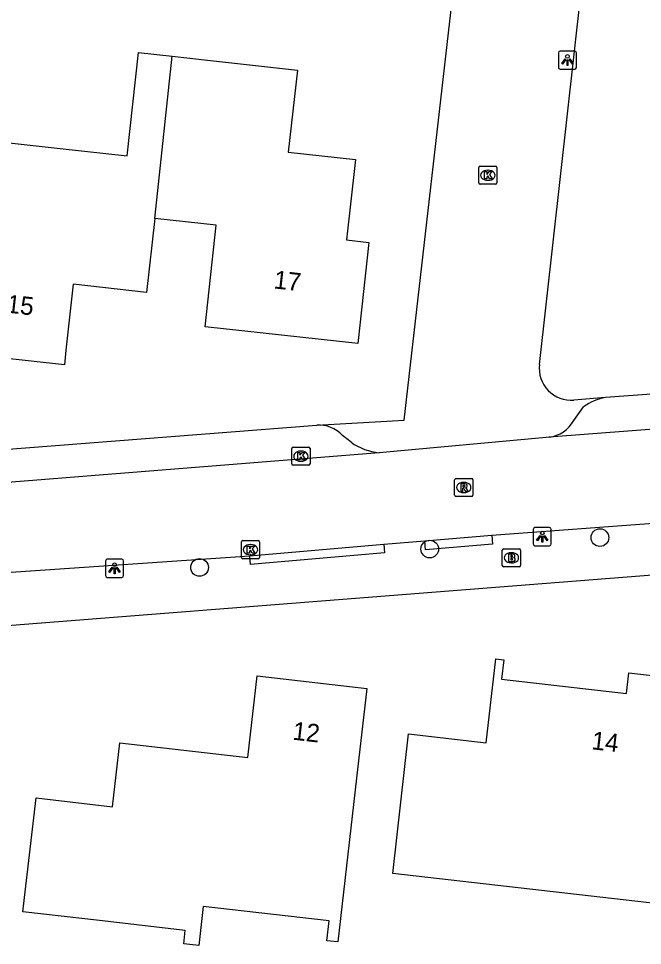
# Model space of a CAD drawing. Extents: x 162398 to 163643, y 386453 to 387397.
# Drawn here: x 163061.6 to 163096.1, y 386543.6 to 386594.8 of the extents above; entities that cross this region are included whole.
import ezdxf

# ---------------------------------------------------------------- set-up
doc = ezdxf.new("R2010")
doc.units = 0
for name, color, linetype in [('IMGEO_Boom', 7, 'Continuous'), ('IMGEO_Brandkraan', 7, 'Continuous'), ('IMGEO_Kolk', 7, 'Continuous'), ('IMGEO_Lichtpunt', 7, 'Continuous'), ('IMGEO_Pand', 7, 'Continuous'), ('IMGEO_Pand_nummerreeks', 7, 'Continuous'), ('IMGEO_Parkeervlak_open', 7, 'Continuous'), ('IMGEO_Rijbaan_lokaal_open', 7, 'Continuous'), ('IMGEO_Rioolput', 7, 'Continuous'), ('IMGEO_Voetpad_open', 7, 'Continuous')]:
    doc.layers.add(name, color=color, linetype=linetype)

msp = doc.modelspace()

# ---------------------------------------------------------------- linework, layer by layer
at = {"layer": 'IMGEO_Boom'}
for centre in [(163093.767, 386566.156), (163084.356, 386565.527), (163071.63, 386564.507)]:
    msp.add_circle(centre, 0.489, dxfattribs=at)
at = {"layer": 'IMGEO_Brandkraan'}
for p, q in [((163088.446, 386565.542), (163089.298, 386565.542)), ((163088.371, 386564.616), (163088.371, 386565.468)), ((163088.859, 386565.322), (163088.884, 386565.322)), ((163089.372, 386565.468), (163089.372, 386564.616)), ((163089.298, 386564.542), (163088.446, 386564.542)), ((163088.882, 386564.762), (163088.857, 386564.762))]:
    msp.add_line(p, q, dxfattribs=at)
for points in [[(163088.446, 386565.542), (163089.298, 386565.542)], [(163088.371, 386564.616), (163088.371, 386565.468)], [(163088.719, 386565.242), (163088.719, 386564.842), (163088.932, 386564.842)], [(163088.95, 386565.242), (163088.719, 386565.242)], [(163088.898, 386565.161), (163088.844, 386565.161), (163088.844, 386565.085)], [(163088.844, 386565.085), (163088.897, 386565.085)], [(163088.906, 386565.009), (163088.844, 386565.009), (163088.844, 386564.928)], [(163089.372, 386565.468), (163089.372, 386564.616)], [(163089.298, 386564.542), (163088.446, 386564.542)], [(163088.844, 386564.928), (163088.906, 386564.928)]]:
    msp.add_lwpolyline(points, dxfattribs=at)
for centre, radius, start, end in [((163088.448, 386565.466), 0.0765, 91.552, 178.448), ((163088.448, 386565.466), 0.0765, 91.552, 178.448), ((163089.296, 386565.466), 0.0765, 1.552, 88.448), ((163089.296, 386565.466), 0.0765, 1.552, 88.448), ((163088.899, 386565.123), 0.0379, 267.8285, 90.9355), ((163088.907, 386564.968), 0.0404, 269.8759, 90.5077), ((163088.954, 386565.097), 0.145, 59.4692, 91.5367), ((163088.979, 386565.144), 0.0922, 285.5137, 58.1501), ((163088.984, 386564.952), 0.105, 301.3115, 78.989), ((163088.448, 386564.618), 0.0765, 181.552, 268.448), ((163088.448, 386564.618), 0.0765, 181.552, 268.448), ((163088.938, 386565.093), 0.251, 268.6676, 293.5347), ((163089.296, 386564.618), 0.0765, 271.552, 358.448), ((163089.296, 386564.618), 0.0765, 271.552, 358.448)]:
    msp.add_arc(centre, radius, start, end, dxfattribs=at)
for centre, major_axis, ratio, start_param, end_param in [((163088.858, 386565.042), (-0.387, 0.002), 0.722429, 4.712389, 7.853982), ((163088.883, 386565.042), (-0.39, 0.002), 0.717154, 1.570796, 4.712389)]:
    msp.add_ellipse(centre, major_axis=major_axis, ratio=ratio, start_param=start_param, end_param=end_param, dxfattribs=at)
at = {"layer": 'IMGEO_Kolk'}
for p, q in [((163087.071, 386585.752), (163087.071, 386586.604)), ((163087.146, 386586.678), (163087.998, 386586.678)), ((163088.072, 386586.604), (163088.072, 386585.752)), ((163087.559, 386586.458), (163087.584, 386586.458)), ((163087.998, 386585.678), (163087.146, 386585.678)), ((163087.582, 386585.898), (163087.557, 386585.898)), ((163076.813, 386571.155), (163077.665, 386571.155)), ((163076.738, 386570.229), (163076.738, 386571.081)), ((163077.226, 386570.935), (163077.251, 386570.935)), ((163077.739, 386571.081), (163077.739, 386570.229)), ((163077.665, 386570.155), (163076.813, 386570.155)), ((163077.249, 386570.375), (163077.224, 386570.375)), ((163073.948, 386565.065), (163073.948, 386565.917)), ((163074.023, 386565.991), (163074.875, 386565.991)), ((163074.436, 386565.771), (163074.461, 386565.771)), ((163074.949, 386565.917), (163074.949, 386565.065)), ((163074.875, 386564.991), (163074.023, 386564.991)), ((163074.459, 386565.211), (163074.434, 386565.211))]:
    msp.add_line(p, q, dxfattribs=at)
for points in [[(163087.071, 386585.752), (163087.071, 386586.604)], [(163087.146, 386586.678), (163087.998, 386586.678)], [(163088.072, 386586.604), (163088.072, 386585.752)], [(163087.392, 386586.378), (163087.515, 386586.378), (163087.515, 386586.227), (163087.645, 386586.378), (163087.809, 386586.378), (163087.663, 386586.227), (163087.816, 386585.978), (163087.664, 386585.978), (163087.579, 386586.142), (163087.515, 386586.075), (163087.515, 386585.978), (163087.392, 386585.978), (163087.392, 386586.378)], [(163087.998, 386585.678), (163087.146, 386585.678)], [(163076.813, 386571.155), (163077.665, 386571.155)], [(163076.738, 386570.229), (163076.738, 386571.081)], [(163077.059, 386570.855), (163077.182, 386570.855), (163077.182, 386570.704), (163077.312, 386570.855), (163077.476, 386570.855), (163077.33, 386570.704), (163077.483, 386570.455), (163077.331, 386570.455), (163077.246, 386570.619), (163077.182, 386570.552), (163077.182, 386570.455), (163077.059, 386570.455), (163077.059, 386570.855)], [(163077.739, 386571.081), (163077.739, 386570.229)], [(163077.665, 386570.155), (163076.813, 386570.155)], [(163073.948, 386565.065), (163073.948, 386565.917)], [(163074.023, 386565.991), (163074.875, 386565.991)], [(163074.269, 386565.691), (163074.392, 386565.691), (163074.392, 386565.54), (163074.522, 386565.691), (163074.686, 386565.691), (163074.54, 386565.54), (163074.693, 386565.291), (163074.541, 386565.291), (163074.456, 386565.455), (163074.392, 386565.388), (163074.392, 386565.291), (163074.269, 386565.291), (163074.269, 386565.691)], [(163074.949, 386565.917), (163074.949, 386565.065)], [(163074.875, 386564.991), (163074.023, 386564.991)]]:
    msp.add_lwpolyline(points, dxfattribs=at)
for centre, start, end in [((163087.148, 386586.602), 91.552, 178.448), ((163087.148, 386586.602), 91.552, 178.448), ((163087.996, 386586.602), 1.552, 88.448), ((163087.996, 386586.602), 1.552, 88.448), ((163087.148, 386585.754), 181.552, 268.448), ((163087.148, 386585.754), 181.552, 268.448), ((163087.996, 386585.754), 271.552, 358.448), ((163087.996, 386585.754), 271.552, 358.448), ((163076.815, 386571.079), 91.552, 178.448), ((163076.815, 386571.079), 91.552, 178.448), ((163077.663, 386571.079), 1.552, 88.448), ((163077.663, 386571.079), 1.552, 88.448), ((163076.815, 386570.231), 181.552, 268.448), ((163076.815, 386570.231), 181.552, 268.448), ((163077.663, 386570.231), 271.552, 358.448), ((163077.663, 386570.231), 271.552, 358.448), ((163074.025, 386565.915), 91.552, 178.448), ((163074.025, 386565.915), 91.552, 178.448), ((163074.873, 386565.915), 1.552, 88.448), ((163074.873, 386565.915), 1.552, 88.448), ((163074.025, 386565.067), 181.552, 268.448), ((163074.025, 386565.067), 181.552, 268.448), ((163074.873, 386565.067), 271.552, 358.448), ((163074.873, 386565.067), 271.552, 358.448)]:
    msp.add_arc(centre, 0.0765, start, end, dxfattribs=at)
for centre, major_axis, ratio, start_param, end_param in [((163087.558, 386586.178), (-0.387, 0.002), 0.722429, 4.712389, 7.853982), ((163087.583, 386586.178), (-0.39, 0.002), 0.717154, 1.570796, 4.712389), ((163077.225, 386570.655), (-0.387, 0.002), 0.722429, 4.712389, 7.853982), ((163077.25, 386570.655), (-0.39, 0.002), 0.717154, 1.570796, 4.712389), ((163074.435, 386565.491), (-0.387, 0.002), 0.722429, 4.712389, 7.853982), ((163074.46, 386565.491), (-0.39, 0.002), 0.717154, 1.570796, 4.712389)]:
    msp.add_ellipse(centre, major_axis=major_axis, ratio=ratio, start_param=start_param, end_param=end_param, dxfattribs=at)
at = {"layer": 'IMGEO_Lichtpunt'}
for p, q in [((163091.472, 386592.946), (163091.472, 386592.139)), ((163091.472, 386592.946), (163091.472, 386592.139)), ((163092.374, 386593.041), (163091.566, 386593.041)), ((163092.374, 386593.041), (163091.566, 386593.041)), ((163092.468, 386592.139), (163092.468, 386592.946)), ((163092.468, 386592.139), (163092.468, 386592.946)), ((163091.566, 386592.045), (163092.374, 386592.045)), ((163091.566, 386592.045), (163092.374, 386592.045)), ((163090.082, 386566.612), (163090.082, 386565.805)), ((163090.082, 386566.612), (163090.082, 386565.805)), ((163090.984, 386566.707), (163090.176, 386566.707)), ((163090.984, 386566.707), (163090.176, 386566.707)), ((163091.078, 386565.805), (163091.078, 386566.612)), ((163091.078, 386565.805), (163091.078, 386566.612)), ((163090.176, 386565.711), (163090.984, 386565.711)), ((163090.176, 386565.711), (163090.984, 386565.711)), ((163066.434, 386564.862), (163066.434, 386564.055)), ((163066.434, 386564.862), (163066.434, 386564.055)), ((163067.336, 386564.957), (163066.528, 386564.957)), ((163067.336, 386564.957), (163066.528, 386564.957)), ((163067.43, 386564.055), (163067.43, 386564.862)), ((163067.43, 386564.055), (163067.43, 386564.862)), ((163066.528, 386563.961), (163067.336, 386563.961)), ((163066.528, 386563.961), (163067.336, 386563.961))]:
    msp.add_line(p, q, dxfattribs=at)
for points in [[(163091.846, 386592.61), (163091.885, 386592.582), (163091.697, 386592.32), (163091.659, 386592.347), (163091.846, 386592.61)], [(163091.948, 386592.562), (163091.995, 386592.562), (163091.995, 386592.24), (163091.948, 386592.24), (163091.948, 386592.562)], [(163092.058, 386592.582), (163092.096, 386592.609), (163092.283, 386592.347), (163092.244, 386592.319), (163092.058, 386592.582)], [(163090.456, 386566.276), (163090.495, 386566.248), (163090.307, 386565.986), (163090.269, 386566.013), (163090.456, 386566.276)], [(163090.558, 386566.228), (163090.605, 386566.228), (163090.605, 386565.906), (163090.558, 386565.906), (163090.558, 386566.228)], [(163090.668, 386566.248), (163090.706, 386566.275), (163090.893, 386566.013), (163090.854, 386565.985), (163090.668, 386566.248)], [(163066.808, 386564.526), (163066.847, 386564.498), (163066.659, 386564.236), (163066.621, 386564.263), (163066.808, 386564.526)], [(163066.91, 386564.478), (163066.957, 386564.478), (163066.957, 386564.156), (163066.91, 386564.156), (163066.91, 386564.478)], [(163067.02, 386564.498), (163067.058, 386564.525), (163067.245, 386564.263), (163067.206, 386564.235), (163067.02, 386564.498)]]:
    msp.add_lwpolyline(points, dxfattribs=at)
for centre in [(163091.971, 386592.744), (163090.581, 386566.41), (163066.933, 386564.66)]:
    msp.add_circle(centre, 0.0994, dxfattribs=at)
for centre, start, end in [((163091.566, 386592.946), 90, 180), ((163091.566, 386592.946), 90, 180), ((163092.374, 386592.946), 0, 90), ((163092.374, 386592.946), 0, 90), ((163091.566, 386592.139), 180, 270), ((163091.566, 386592.139), 180, 270), ((163092.374, 386592.139), 270, 0), ((163092.374, 386592.139), 270, 360), ((163090.176, 386566.612), 90, 180), ((163090.176, 386566.612), 90, 180), ((163090.984, 386566.612), 0, 90), ((163090.984, 386566.612), 0, 90), ((163090.176, 386565.805), 180, 270), ((163090.176, 386565.805), 180, 270), ((163090.984, 386565.805), 270, 0), ((163090.984, 386565.805), 270, 360), ((163066.528, 386564.862), 90, 180), ((163066.528, 386564.862), 90, 180), ((163067.336, 386564.862), 0, 90), ((163067.336, 386564.862), 0, 90), ((163066.528, 386564.055), 180, 270), ((163066.528, 386564.055), 180, 270), ((163067.336, 386564.055), 270, 0), ((163067.336, 386564.055), 270, 360)]:
    msp.add_arc(centre, 0.0946, start, end, dxfattribs=at)
at = {"layer": 'IMGEO_Pand'}
for points in [[(163069.151, 386583.79), (163068.699, 386579.705), (163064.649, 386580.153), (163064.247, 386576.515), (163064.157, 386575.703), (163058.609, 386576.317), (163058.711, 386577.241), (163055.828, 386577.56), (163056.378, 386582.53), (163056.669, 386585.159), (163056.892, 386587.171), (163060.807, 386586.737), (163060.947, 386587.994), (163063.925, 386587.664), (163067.626, 386587.254), (163068.258, 386592.966), (163070.126, 386592.759)], [(163070.126, 386592.759), (163072.07, 386592.544), (163077.039, 386591.994), (163076.538, 386587.463), (163080.245, 386587.053), (163079.753, 386582.609), (163080.998, 386582.471), (163080.38, 386576.878), (163071.935, 386577.812), (163072.554, 386583.414), (163069.151, 386583.79)], [(163069.151, 386583.79), (163070.126, 386592.759)], [(163082.311, 386547.598), (163083.189, 386555.309), (163087.476, 386554.821), (163088.006, 386559.453), (163088.447, 386559.403), (163088.324, 386558.334), (163095.242, 386557.543), (163095.372, 386558.687), (163100.995, 386558.044), (163100.427, 386553.077), (163099.576, 386545.625), (163082.311, 386547.598)], [(163079.274, 386543.815), (163078.665, 386543.885), (163078.79, 386544.973), (163071.837, 386545.77), (163071.59, 386543.621), (163070.758, 386543.716), (163070.842, 386544.448), (163066.099, 386544.993), (163061.853, 386545.481), (163062.59, 386551.77), (163066.821, 386551.284), (163067.227, 386554.82), (163074.295, 386554.009), (163074.812, 386558.52), (163080.882, 386557.824), (163080.312, 386552.857), (163079.274, 386543.815)]]:
    msp.add_lwpolyline(points, dxfattribs=at)
at = {"layer": 'IMGEO_Parkeervlak_open'}
for points in [[(163132.203, 386576.666), (163094.081, 386573.893)], [(163002.915, 386566.435), (163004.014, 386566.483), (163022.198, 386568.023), (163078.11, 386572.372)]]:
    msp.add_lwpolyline(points, dxfattribs=at)
at = {"layer": 'IMGEO_Rijbaan_lokaal_open'}
for points in [[(163135.627, 386575.115), (163090.964, 386571.703)], [(163090.964, 386571.703), (163090.794, 386571.688), (163081.567, 386570.85)], [(163081.567, 386570.85), (163000.058, 386564.345), (162999.956, 386564.347)], [(163087.793, 386566.294), (163096.974, 386566.98)], [(163084.079, 386565.981), (163087.793, 386566.294)], [(163074.412, 386565.159), (163081.812, 386565.794)], [(163081.812, 386565.794), (163084.079, 386565.981)], [(163060.944, 386564.22), (163074.412, 386565.159)]]:
    msp.add_lwpolyline(points, dxfattribs=at)
at = {"layer": 'IMGEO_Rioolput'}
for p, q in [((163085.736, 386568.5), (163085.736, 386569.352)), ((163085.811, 386569.426), (163086.663, 386569.426)), ((163086.224, 386569.206), (163086.249, 386569.206)), ((163086.737, 386569.352), (163086.737, 386568.5)), ((163086.247, 386568.646), (163086.222, 386568.646)), ((163086.663, 386568.426), (163085.811, 386568.426))]:
    msp.add_line(p, q, dxfattribs=at)
for points in [[(163085.736, 386568.5), (163085.736, 386569.352)], [(163085.811, 386569.426), (163086.663, 386569.426)], [(163086.325, 386569.124), (163086.073, 386569.126), (163086.073, 386568.726)], [(163086.737, 386569.352), (163086.737, 386568.5)], [(163086.073, 386568.726), (163086.197, 386568.726), (163086.197, 386568.888), (163086.208, 386568.888)], [(163086.251, 386569.045), (163086.197, 386569.045), (163086.197, 386568.964)], [(163086.197, 386568.964), (163086.249, 386568.964)], [(163086.255, 386568.859), (163086.326, 386568.726), (163086.466, 386568.726), (163086.401, 386568.852)], [(163086.663, 386568.426), (163085.811, 386568.426)]]:
    msp.add_lwpolyline(points, dxfattribs=at)
for centre, radius, start, end in [((163085.813, 386569.35), 0.0765, 91.552, 178.448), ((163085.813, 386569.35), 0.0765, 91.552, 178.448), ((163086.324, 386569.014), 0.109, 350.3612, 89.416), ((163086.661, 386569.35), 0.0765, 1.552, 88.448), ((163086.661, 386569.35), 0.0765, 1.552, 88.448), ((163086.207, 386568.835), 0.0533, 26.0293, 88.6989), ((163086.233, 386569.153), 0.19, 274.7715, 282.9687), ((163086.257, 386568.949), 0.0964, 77.0061, 93.1865), ((163086.271, 386569.006), 0.0378, 276.6634, 79.6772), ((163086.322, 386569.014), 0.112, 277.5842, 350.9817), ((163086.306, 386568.799), 0.108, 29.5134, 73.7905), ((163085.813, 386568.502), 0.0765, 181.552, 268.448), ((163085.813, 386568.502), 0.0765, 181.552, 268.448), ((163086.661, 386568.502), 0.0765, 271.552, 358.448), ((163086.661, 386568.502), 0.0765, 271.552, 358.448)]:
    msp.add_arc(centre, radius, start, end, dxfattribs=at)
for centre, major_axis, ratio, start_param, end_param in [((163086.223, 386568.926), (-0.387, 0.002), 0.722429, 4.712389, 7.853982), ((163086.248, 386568.926), (-0.39, 0.002), 0.717154, 1.570796, 4.712389)]:
    msp.add_ellipse(centre, major_axis=major_axis, ratio=ratio, start_param=start_param, end_param=end_param, dxfattribs=at)
at = {"layer": 'IMGEO_Voetpad_open'}
for points in [[(163090.42, 386575.726), (163097.29, 386637.077)], [(163078.11, 386572.372), (163082.937, 386572.643), (163085.957, 386598.897), (163082.131, 386599.35), (163084.149, 386617.704)], [(163094.081, 386573.893), (163092.322, 386573.754)], [(163092.319, 386572.623), (163092.866, 386573.385)], [(163078.116, 386572.369), (163078.11, 386572.372)], [(163080.013, 386571.423), (163079.532, 386571.807)], [(163139.616, 386567.455), (163000, 386556.492), (162997.872, 386556.325)], [(163087.793, 386566.294), (163087.83, 386565.796), (163084.116, 386565.483), (163084.079, 386565.981)], [(163081.812, 386565.794), (163081.848, 386565.322), (163074.449, 386564.673), (163074.412, 386565.159)]]:
    msp.add_lwpolyline(points, dxfattribs=at)
for centre, radius, start, end in [((163092.185, 386575.525), 1.776, 173.4909, 274.4387), ((163094.546, 386571.073), 2.858, 99.3703, 126.01), ((163078.221, 386570.569), 1.803, 43.3625, 93.3419), ((163090.694, 386573.558), 1.875, 278.2728, 330.0776), ((163081.856, 386574.028), 3.191, 234.7202, 264.7993)]:
    msp.add_arc(centre, radius, start, end, dxfattribs=at)

# ---------------------------------------------------------------- texts
at = {"layer": 'IMGEO_Pand_nummerreeks'}
for s, rotation, p in [('17', 353.6888, (163075.704, 386579.93)), ('15', 353.6847, (163060.93, 386578.595)), ('12', 353.4589, (163076.74, 386554.998)), ('14', 353.4772, (163093.271, 386554.467))]:
    msp.add_text(s, height=1, rotation=rotation, dxfattribs=at).set_placement(p)

doc.saveas('drawing.dxf')
